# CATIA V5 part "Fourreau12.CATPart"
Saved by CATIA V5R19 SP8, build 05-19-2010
Part number: Fourreau12
Bounding box of the stored display mesh (mm): x -125 to -115, y 147.799 to 194.645, z 43.424 to 83.832
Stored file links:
  G:\EU_thinkMotion\CFAO_2010\MMS_groupe2\MMS_groupe2\A reprendre\jcauchy\Fourreau12.CATPart
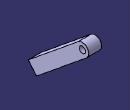
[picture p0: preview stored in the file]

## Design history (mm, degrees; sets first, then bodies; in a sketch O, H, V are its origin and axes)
Parameters
  Rayontige_fourreau12 = 5 mm
  Longueurfourreau_fourreau12 = 50 mm
  Hauteurfourreau_fourreau12 = 10 mm
  Largeurfourreau_fourreau12 = 10 mm
  Rayonfixation_fourreau12 = 2.5 mm
Set1
  Plane1: stored without definition
  Sketch1 on Plane1, origin (-120, 0, 0), H (0, -1, 0), V (0, 0, 1)
    line L1 (-192.8693, 75.0209) -> (-154.118, 43.4244)
    point P1 (-192.8693, 75.0209)
    arc A1 centre (-189.7097, 78.896) radius 5 from (-186.55, 82.7711) to (-192.8693, 75.0209) ccw
    point P4 (-186.55, 82.7711)
    point P5 (-192.8693, 75.0209)
    line L2 (-186.55, 82.7711) -> (-147.7987, 51.1746)
    point P6 (-186.55, 82.7711)
    line L3 (-154.118, 43.4244) -> (-147.7987, 51.1746)
    length L1 = 50 {= Longueurfourreau_fourreau12}
    length L3 = 10 {= Largeurfourreau_fourreau12}
    tangency: A1 L1, L2 A1
    perpendicularity: L1 L3, L3 L2
    coincidence: P4 P6, P5 P1
  Point1: stored without definition
  Plane2: stored without definition
  Plane3: stored without definition
Body1 (main body)
  Pad1: profile Sketch1, direction (-1, 0, 0), length 5 {= Hauteurfourreau_fourreau12 /2}, mirrored extent
  Sketch2 on start face of Pad1, origin (-115, 186.5977, 77.3431), H (0, 1, 0), V (0, 0, 1)
    point P1 (3.112, 1.5529)
    reference projected arc E1 centre (3.112, 1.5529) radius 5 from (6.2716, -2.3222) to (-0.0477, 5.428) ccw from edge [start face of Pad1 | face of Pad1 from Sketch1.A1]
    distance P1 E1 = 5 {= Largeurfourreau_fourreau12 /2}
  Hole1: placed by Sketch2, at (-115, 189.7097, 78.896) direction (-1, 0, 0), diameter 5 {= Rayonfixation_fourreau12 *2}, depth 20
  Sketch3 on face of Pad1 from Sketch1.L3, origin (-121.5114, 151.9135, 46.1281), H (1, 0, 0), V (0, -0.6319, 0.775)
    point P1 (1.5114, 1.5114)
    reference projected line E1 (6.5114, -3.4886) -> (6.5114, 6.5114) from edge [start face of Pad1 | face of Pad1 from Sketch1.L3]
    reference projected line E2 (6.5114, 6.5114) -> (-3.4886, 6.5114) from edge [face of Pad1 from Sketch1.L2 | face of Pad1 from Sketch1.L3]
    distance P1 E1 = 5 {= Hauteurfourreau_fourreau12 /2}
    distance P1 E2 = 5 {= Largeurfourreau_fourreau12 /2}
  Hole2: placed by Sketch3, at (-120, 150.9584, 47.2995) direction (0, 0.775, 0.6319), diameter 5 {= Rayontige_fourreau12}, depth 20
